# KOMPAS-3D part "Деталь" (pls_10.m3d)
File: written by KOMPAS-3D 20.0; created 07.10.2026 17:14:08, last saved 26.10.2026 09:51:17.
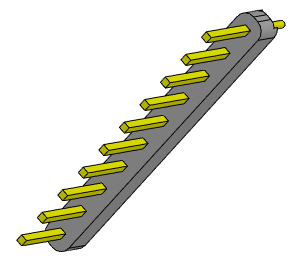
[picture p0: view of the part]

Document properties: Полное имя файла: D:\myProjects\Progect_esp32\box_compas\разъемы\pls_10.m3d

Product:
- Part/product: Деталь
    Масса: 0.00128744
  - Body: Тело 1
      Масса: 0.00130352
  - Body: Тело 2
      Масса: 0.00130352
  - Body: Тело 3
      Масса: 0.00130352

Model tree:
1. Эскиз:1
2. Элемент выдавливания:1
     Расстояние 1 = 2.5
3. Эскиз:2  (with: Элемент выдавливания:1)
4. Элемент выдавливания:2
     Расстояние 1 = 6
5. Массив по сетке:1  (with: Элемент выдавливания:2, Эскиз:2)  (10 pattern instances)
     Шаг 1 = 2.54; Угол раствора = 90
6. Эскиз:3  (with: Элемент выдавливания:1)
7. Элемент выдавливания:3
     Расстояние 1 = 3
8. Массив по сетке:2  (with: Элемент выдавливания:3, Эскиз:3)  (10 pattern instances)
     Шаг 1 = 2.54; Угол раствора = 90; Геометрический массив = 128
9. Эскиз:4  (with: Элемент выдавливания:1)
10. Элемент выдавливания:4
     Расстояние 2 = 25.4
11. Скругление:1  (with: Элемент выдавливания:1)
     Радиус = 1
